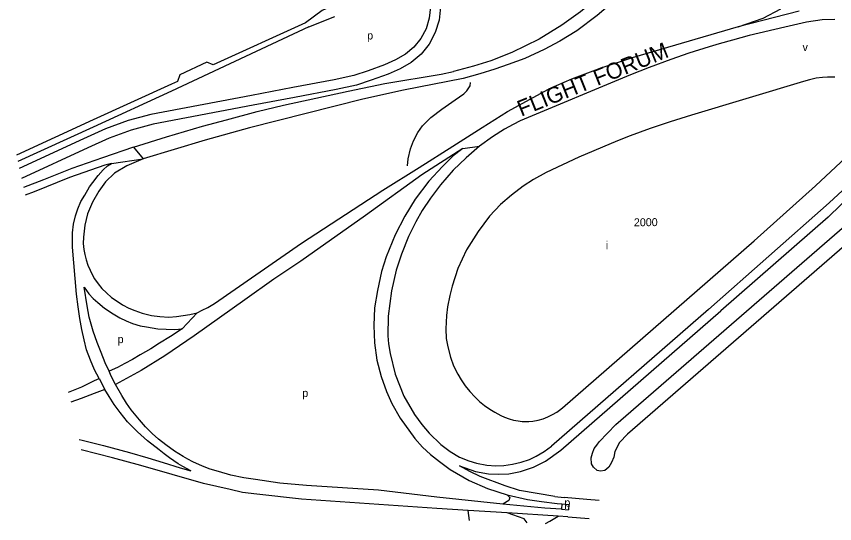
# Model space of a CAD drawing. Extents: x 154765 to 156627, y 383996 to 386132.
# Drawn here: x 155577.2 to 155986.3, y 383995.8 to 384249.3 of the extents above; entities that cross this region are included whole.
import ezdxf

# ---------------------------------------------------------------- set-up
doc = ezdxf.new("R2010")
doc.units = 0
for name, color, linetype in [('BLT_Basislijn', 7, 'Continuous'), ('BLT_Bebouwing', 7, 'Continuous'), ('BLT_Centroide', 7, 'Continuous'), ('BLT_Huisnummer', 7, 'Continuous'), ('BLT_Straatnaam_hoofdweg', 7, 'Continuous'), ('BLT_Vlakafsluiter', 7, 'Continuous')]:
    doc.layers.add(name, color=color, linetype=linetype)

msp = doc.modelspace()

# ---------------------------------------------------------------- linework, layer by layer
at = {"layer": 'BLT_Basislijn'}
for p, q in [((155723.41, 384244), (155736.36, 384249.3)), ((155721.76, 384246.02), (155675.52, 384225.05)), ((155723.41, 384244), (155660.03, 384214.41)), ((155935.22, 384237.46), (155928.62, 384235.56)), ((155943.51, 384239.73), (155935.22, 384237.46)), ((155923.59, 384234.08), (155913.42, 384230.92)), ((155928.62, 384235.56), (155923.59, 384234.08)), ((155913.42, 384230.92), (155904.44, 384227.76)), ((155904.44, 384227.76), (155893.58, 384223.71)), ((155884.3, 384220.06), (155829.14, 384197.18)), ((155893.58, 384223.71), (155884.3, 384220.06)), ((155654.76, 384211.99), (155615.54, 384194.01)), ((155660.03, 384214.41), (155654.76, 384211.99)), ((155615.62, 384197.61), (155577.18, 384179.93)), ((155615.54, 384194.01), (155577.87, 384176.8)), ((155923.24, 384102.87), (155844.67, 384034.51)), ((155849.46, 384032.56), (155929.31, 384102.14)), ((155618.65, 384068.37), (155621.37, 384062.82)), ((155846.45, 384009.39), (155850.98, 384008.97)), ((155849.93, 384005.75), (155849.75, 384003.03)), ((155849.93, 384005.75), (155853.42, 384005.43)), ((155853.42, 384005.43), (155853.25, 384002.78)), ((155803.78, 383997.38), (155803.03, 384002.4)), ((155822.61, 384001.16), (155803.03, 384002.4)), ((155849.75, 384003.03), (155853.25, 384002.78)), ((155852.85, 383999.25), (155863.63, 383998.34))]:
    msp.add_line(p, q, dxfattribs=at)
for points in [[(155703.05, 384471.71), (155704.65, 384454.77), (155706.01, 384440.35), (155707.47, 384424.81), (155708.96, 384413.13), (155710.77, 384403.94), (155714.1, 384392.31), (155718.36, 384380.76), (155724.85, 384366.97), (155731.84, 384353.7), (155745.31, 384330.12), (155759.92, 384305.12), (155772.44, 384283.05), (155782.28, 384264.93), (155783.76, 384259.45), (155784.28, 384254.07), (155783.61, 384248.39), (155782, 384243.15), (155779.4, 384238.16), (155775.96, 384233.98)], [(155761.61, 384312.12), (155764.25, 384307.61), (155776.81, 384285.47), (155786.95, 384266.8), (155788.7, 384260.35), (155789.31, 384254.02), (155788.52, 384247.35), (155786.64, 384241.25), (155783.6, 384235.39), (155779.52, 384230.44)], [(155880.57, 384271.55), (155875.35, 384265.99), (155867.6, 384258.51), (155859.16, 384251.55), (155849.87, 384244.94), (155838.55, 384237.95), (155824.89, 384231.23), (155814.41, 384227.03), (155805.76, 384224.34), (155795.71, 384221.73)], [(155755.85, 384264.01), (155730.1, 384252.3), (155721.76, 384246.02)], [(155883.66, 384264.54), (155876.37, 384257.21), (155867.57, 384249.7), (155857.42, 384242.15), (155848.96, 384236.9), (155841.08, 384232.67), (155831.46, 384228.24), (155823.11, 384225.18), (155816.36, 384222.9), (155808.84, 384220.52), (155800.62, 384218.26)], [(155937.99, 384244.01), (155950.63, 384248.43), (155959.45, 384253.1)], [(155972.23, 384246.35), (155961.42, 384243.86), (155943.51, 384239.73)], [(155986.43, 384247.71), (155980.1, 384247.52), (155972.23, 384246.35)], [(155937.99, 384244.01), (155884.98, 384228.55), (155869.39, 384223.35), (155854.75, 384217.92), (155843.18, 384212.96)], [(155775.96, 384233.98), (155771.73, 384230.43), (155766.73, 384227.51), (155761.21, 384225.1), (155753.02, 384222.15), (155745.84, 384219.81), (155735.99, 384217.63), (155715.37, 384213.73), (155694.72, 384209.82), (155644.46, 384200.31), (155633.14, 384197.29), (155621.68, 384193.09), (155610.81, 384188.1), (155578.63, 384173.35)], [(155779.52, 384230.44), (155774.61, 384226.33), (155769, 384223.05), (155763.06, 384220.45), (155754.64, 384217.42), (155747.16, 384214.98), (155736.99, 384212.74), (155716.3, 384208.82), (155695.65, 384204.91), (155645.57, 384195.43), (155634.65, 384192.52), (155623.58, 384188.46), (155612.89, 384183.56), (155579.73, 384168.35)], [(155675.52, 384225.05), (155672.46, 384226.39), (155658.92, 384220.11), (155657.77, 384216.82), (155654.76, 384215.44)], [(155635.67, 384183.87), (155652.23, 384189.07), (155670.25, 384194.4), (155682.18, 384197.68), (155697.53, 384201.71), (155710.72, 384204.97), (155743.14, 384212.01), (155761.46, 384215.68), (155789.51, 384220.47), (155795.71, 384221.73)], [(155800.62, 384218.26), (155770.81, 384212.47), (155750.36, 384207.85), (155693.73, 384193.55), (155671.6, 384187.47), (155640.65, 384178.12)], [(155772.78, 384174.58), (155773.01, 384178.07), (155774.19, 384183.19), (155775.66, 384187.03), (155777.93, 384191.22), (155780.26, 384194.55), (155784.43, 384198.85), (155789.9, 384202.98), (155796.52, 384207.57), (155800.9, 384210.62), (155802.47, 384212.09), (155804.1, 384214.56), (155804.29, 384216.19)], [(155654.76, 384215.44), (155615.62, 384197.61)], [(155667.65, 384101.21), (155670.13, 384102.51), (155672.85, 384103.81), (155676.27, 384105.81), (155719.73, 384135.94), (155760.46, 384162.4), (155778.53, 384173.86), (155795.41, 384184.49), (155810.06, 384193.82), (155822.69, 384201.85), (155843.18, 384212.95)], [(155829.14, 384197.18), (155825.53, 384195.34), (155821.21, 384192.89), (155815.2, 384189.1), (155808.72, 384184.39)], [(156032.7, 384197.21), (155982.99, 384149.03), (155929.31, 384102.14)], [(156025.06, 384194.36), (155983.47, 384156.08), (155923.24, 384102.87)], [(155635.67, 384183.87), (155620.24, 384178.7), (155604.89, 384173.26), (155590.72, 384167.59), (155580.75, 384163.74)], [(155800.34, 384183.36), (155779.89, 384170.19), (155751.78, 384149.88), (155719.43, 384126.96), (155705.97, 384117.98), (155691.33, 384107.59), (155678.81, 384098.61), (155666.06, 384089.63), (155651.42, 384079.71), (155639.61, 384072.38), (155626.69, 384065.44)], [(155808.72, 384184.39), (155801.98, 384178.69), (155795.56, 384172.4), (155789.22, 384165.11), (155784.25, 384158.5), (155780.14, 384152.24), (155776.97, 384146.71), (155773.3, 384139.34), (155769.69, 384130.48), (155767.09, 384122.45), (155764.75, 384112.22), (155763.04, 384099.48), (155762.95, 384089.74), (155763.31, 384085.72), (155763.99, 384080.89), (155766.54, 384070.45), (155770.93, 384059.51), (155776.25, 384050.32), (155779.86, 384045.42), (155783.54, 384041.12), (155789.46, 384035.33), (155793.98, 384031.89), (155798.74, 384029.13), (155803.38, 384027.21), (155807.25, 384026.07), (155812.47, 384025.1), (155816.91, 384024.8), (155820.86, 384024.94), (155825.24, 384025.51), (155829.55, 384026.51), (155833.65, 384027.93), (155837.14, 384029.57), (155840.99, 384031.82), (155844.67, 384034.51)], [(155800.34, 384183.36), (155795.58, 384179.63)], [(155795.58, 384179.63), (155790.25, 384174.35), (155783.44, 384166.94), (155776.53, 384157.89), (155771.33, 384149.47), (155766.49, 384140.13), (155762.14, 384129.08), (155759.79, 384121.81), (155757.72, 384112.4), (155756.3, 384103.64), (155755.86, 384094.77), (155756.19, 384086.23), (155757.48, 384077.44), (155759.56, 384069.28), (155762.18, 384061.83), (155764.93, 384055.91), (155769.09, 384048.6), (155776.44, 384038.46), (155780.19, 384034.1), (155784.31, 384030.35), (155788.68, 384026.94)], [(155618.65, 384068.37), (155616.29, 384072.62), (155614.28, 384077.46), (155612.27, 384082.66), (155611.09, 384087.74), (155609.91, 384092.82), (155608.97, 384098.37), (155608.14, 384104.16), (155607.31, 384110.54), (155605.19, 384134.05), (155605.19, 384137.47), (155605.31, 384141.13), (155605.78, 384145.5), (155606.72, 384149.64), (155607.91, 384153.06), (155609.44, 384156.73), (155611.33, 384160.03), (155613.81, 384164.05), (155615.46, 384166.29), (155618.06, 384169.72), (155620.66, 384172.67), (155622.67, 384174.68), (155624.67, 384175.86)], [(155640.65, 384178.12), (155632.4, 384174.68), (155626.26, 384170.9), (155621.78, 384166.65), (155618.47, 384161.92), (155615.17, 384156.49), (155612.8, 384150.58), (155611.39, 384144.91), (155610.68, 384139.01), (155610.62, 384135.82), (155610.86, 384132.87), (155611.33, 384130.27), (155612.04, 384127.67), (155612.98, 384125.07), (155614.04, 384122.47), (155615.11, 384120.34), (155616.29, 384118.1), (155618.06, 384115.62), (155619.95, 384113.26), (155622.31, 384111.13), (155624.79, 384108.89), (155627.62, 384107), (155630.22, 384105.22), (155633.41, 384103.57), (155636.36, 384102.27), (155640.14, 384100.97), (155644.74, 384099.79), (155648.88, 384099.32), (155653.36, 384099.08), (155657.26, 384099.32), (155660.57, 384099.79), (155663.87, 384100.26), (155667.65, 384101.21)], [(155624.67, 384175.86), (155621.43, 384174.92)], [(155621.43, 384174.92), (155603.71, 384168.77), (155586, 384161.69), (155581.58, 384159.96)], [(155876.92, 384045.31), (156000, 384152.12)], [(156000, 384142.36), (155882.67, 384040.61)], [(155623.52, 384072), (155621.66, 384076.16), (155619.65, 384081.36), (155617.65, 384086.32), (155615.64, 384091.99), (155613.63, 384098.96), (155612.57, 384104.63), (155611.03, 384113.96), (155613.4, 384110.65), (155615.52, 384108.41), (155617.88, 384106.28), (155621.19, 384103.45), (155625.56, 384100.61), (155628.86, 384098.72), (155632.05, 384097.19), (155635.24, 384095.89), (155639.14, 384094.71), (155642.21, 384094.12), (155647.87, 384093.17), (155652.13, 384092.93), (155656.49, 384092.82), (155660.15, 384093.17)], [(155660.15, 384093.17), (155654.25, 384089.39), (155648.7, 384085.97), (155644.33, 384083.25), (155639.02, 384080.18), (155635.24, 384077.93), (155631.46, 384075.81), (155627.68, 384073.8), (155623.52, 384072)], [(155626.69, 384065.44), (155624.61, 384069.55), (155623.52, 384072)], [(155603.28, 384061.58), (155605.78, 384062.46), (155609.91, 384064.23), (155612.98, 384065.65), (155616.29, 384067.3), (155618.65, 384068.37)], [(155820.39, 384005.54), (155787.47, 384009.13), (155758.28, 384012.49), (155722.26, 384014.85), (155708.92, 384016.04), (155696.76, 384017.81), (155690.97, 384018.75), (155684.36, 384020.05), (155678.22, 384021.82), (155674.09, 384023.12), (155671.14, 384024.19), (155668.66, 384025.25), (155665.47, 384026.79), (155662.99, 384028.08), (155660.51, 384029.38), (155656.26, 384031.98), (155651.89, 384035.17), (155648.23, 384038.01), (155645.04, 384040.84), (155641.73, 384044.27), (155638.66, 384047.69), (155634.53, 384052.66), (155632.29, 384056.08), (155629.93, 384059.86), (155626.69, 384065.44)], [(155621.37, 384062.82), (155616.05, 384060.93), (155609.56, 384058.33), (155604.38, 384056.57)], [(155608.5, 384037.88), (155610.03, 384037.54), (155615.46, 384036.24), (155620.78, 384034.94), (155633.77, 384031.39), (155642.98, 384028.68), (155650.53, 384026.31), (155659.15, 384023.72), (155664.47, 384022.18), (155662.58, 384023.24), (155660.45, 384024.42), (155658.09, 384025.72), (155655.96, 384027.14), (155653.72, 384028.8), (155651.12, 384030.69), (155648.53, 384032.69), (155642.74, 384037.18), (155637.78, 384041.79), (155632.7, 384046.63), (155629.04, 384051.36), (155626.09, 384055.37), (155623.61, 384059.39), (155621.37, 384062.82)], [(155882.67, 384040.61), (155878.64, 384036.34), (155876.31, 384031.85), (155875.82, 384029.11), (155874.78, 384026.33), (155873.39, 384024.03), (155871.46, 384022.37), (155869.21, 384022.01), (155867.64, 384022.46), (155865.75, 384024.12), (155864.76, 384025.79), (155864.58, 384028.75), (155865.3, 384031.04), (155866.02, 384033.34), (155867.32, 384035.04), (155868.63, 384036.75), (155876.92, 384045.31)], [(155803.03, 384002.4), (155787.33, 384003.4), (155719.79, 384008.12), (155697.35, 384010.49), (155690.27, 384011.43), (155684.13, 384012.85), (155670.67, 384015.92), (155639.49, 384024.9), (155625.32, 384028.68), (155609.65, 384032.65)], [(155798.67, 384024.78), (155806.77, 384021.9), (155813.23, 384020.78), (155818.35, 384020.64), (155823.46, 384020.79), (155829.21, 384021.87), (155835.69, 384024.03), (155841.8, 384027.05), (155849.46, 384032.56)], [(155788.68, 384026.94), (155794.14, 384022.91)], [(155846.45, 384009.39), (155828.78, 384012.34), (155821.62, 384014.67), (155809.01, 384019.34), (155803.85, 384021.87), (155798.67, 384024.78)], [(155794.14, 384022.91), (155803.55, 384017.47), (155812.71, 384013.39), (155822.53, 384010.19)], [(155822.53, 384010.19), (155823.91, 384008.84), (155823.47, 384007.4), (155820.39, 384005.54)], [(155822.53, 384010.19), (155832.72, 384007.9), (155839.67, 384006.95), (155847.53, 384005.98), (155849.93, 384005.75)], [(155868.52, 384007.45), (155862.33, 384007.91), (155850.98, 384008.97)], [(155849.75, 384003.03), (155841.35, 384003.63), (155820.39, 384005.54)], [(155832.58, 383996.24), (155831.04, 383998.19), (155822.61, 384001.16)], [(155848.07, 383999.55), (155822.61, 384001.16)], [(155841.65, 383995.85), (155843.86, 383997.12), (155848.07, 383999.55)], [(155852.85, 383999.25), (155848.07, 383999.55)]]:
    msp.add_lwpolyline(points, dxfattribs=at)
at = {"layer": 'BLT_Bebouwing'}
for points in [[(155986.33, 384218.98), (155982.79, 384218.98), (155980.17, 384218.74), (155976.97, 384218.34), (155973.65, 384217.64), (155970.68, 384216.83), (155914.68, 384199.97), (155904.02, 384196.63), (155894.12, 384193.26), (155883.99, 384189.56), (155877.76, 384187.13), (155858.36, 384178.94), (155842.06, 384171.22), (155835.77, 384167.76), (155830.49, 384164.42), (155824.65, 384159.97), (155819.27, 384155.24), (155813.71, 384149.39), (155808.01, 384141.89), (155802.23, 384132.7), (155797.94, 384123.26), (155795.01, 384114.43), (155793.84, 384109.86), (155792.76, 384104.24), (155792.15, 384099.84)], [(155792.15, 384099.84), (155791.84, 384093.14), (155792.14, 384088.4), (155792.83, 384084.12), (155794.28, 384079), (155795.81, 384074.65), (155797.9, 384070.55), (155799.53, 384067.71), (155801.63, 384064.66), (155803.92, 384061.83), (155806.33, 384059.27), (155808.81, 384056.9), (155811.25, 384054.95), (155813.89, 384053.04), (155816.37, 384051.47), (155819.39, 384049.84), (155821.19, 384049.02), (155823.56, 384048.14), (155825.73, 384047.53), (155828.01, 384047.17), (155830.09, 384046.95), (155831.78, 384046.92), (155833.36, 384046.92), (155835.41, 384047.12), (155838, 384047.57), (155840.61, 384048.27), (155842.94, 384049.17), (155845.27, 384050.3), (155847.34, 384051.56), (155848.68, 384052.49), (155850.24, 384053.76), (155946.13, 384137.07), (155976.77, 384164.62), (156006.85, 384192.8)]]:
    msp.add_lwpolyline(points, dxfattribs=at)
at = {"layer": 'BLT_Vlakafsluiter'}
for p, q in [((155968.5, 384251.86), (155937.99, 384244.01)), ((155635.67, 384183.87), (155640.65, 384178.12)), ((155800.34, 384183.36), (155808.72, 384184.39)), ((155624.67, 384175.86), (155640.65, 384178.12)), ((155660.15, 384093.17), (155667.65, 384101.21))]:
    msp.add_line(p, q, dxfattribs=at)

# ---------------------------------------------------------------- texts
at = {"layer": 'BLT_Centroide'}
for s, p in [('p', (155752.56, 384237.74)), ('v', (155970.24, 384231.95)), ('i', (155871.89, 384132.94)), ('p', (155627.81, 384086.04)), ('p', (155720.13, 384059.1)), ('p', (155851.18, 384004.38))]:
    msp.add_text(s, height=4, dxfattribs=at).set_placement(p)
at = {"layer": 'BLT_Huisnummer'}
msp.add_text('2000', height=4, rotation=0.466, dxfattribs=at).set_placement((155885.92, 384144.39))
at = {"layer": 'BLT_Straatnaam_hoofdweg'}
msp.add_text('FLIGHT FORUM', height=8, rotation=22, dxfattribs=at).set_placement((155829.59, 384199.12))

doc.saveas('drawing.dxf')
